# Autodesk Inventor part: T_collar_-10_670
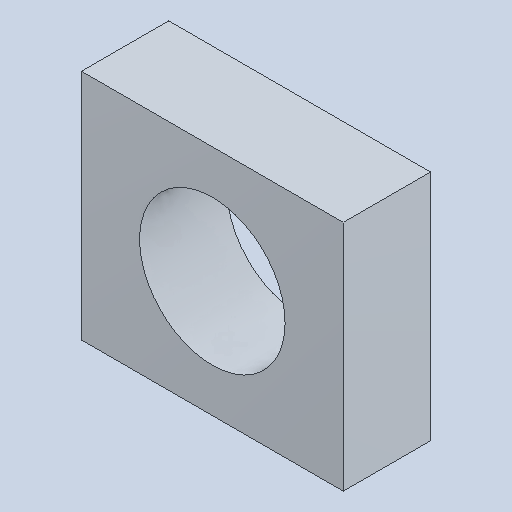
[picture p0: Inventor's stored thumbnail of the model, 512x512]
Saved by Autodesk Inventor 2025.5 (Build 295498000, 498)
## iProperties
Created: 2026-10
Part Number: T_collar_-10_670
Material: Genérico
Document SubType Name: Modeling
Designer: Luis M
Density: 1 g/cm^3
Appearance: Valor por defecto
Author: Luis M
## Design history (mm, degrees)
feature "Base1"
node "Sólido1"
